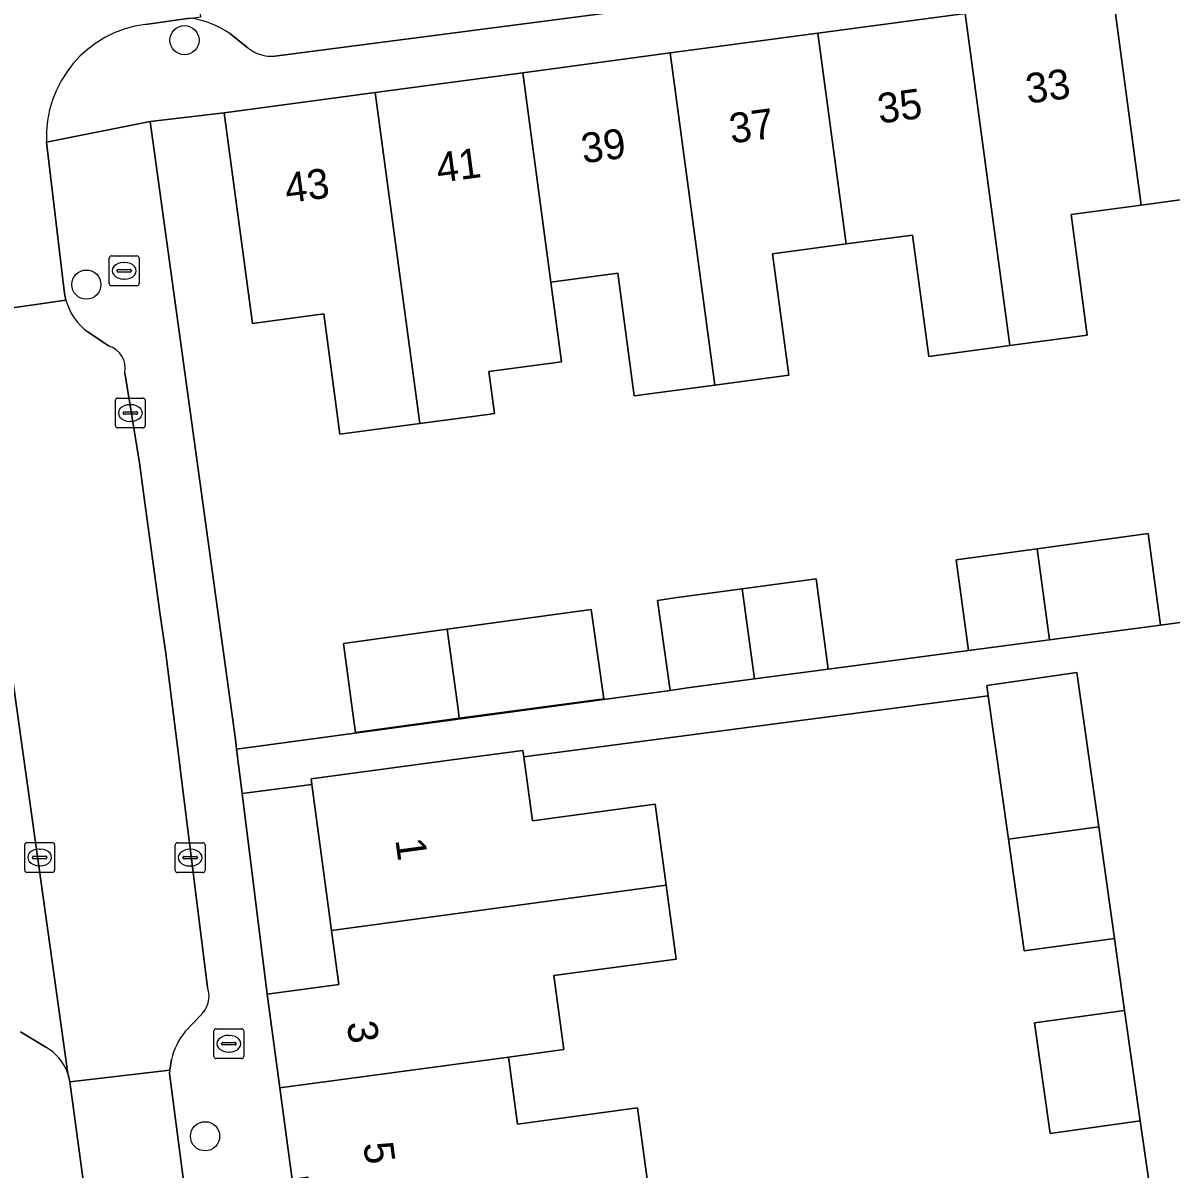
# Model space of a CAD drawing. Extents: x 163147 to 163550, y 380933 to 381639.
# Drawn here: x 163253.82 to 163292.27, y 381438.36 to 381476.76 of the extents above; entities that cross this region are included whole.
import ezdxf

# ---------------------------------------------------------------- set-up
doc = ezdxf.new("R2010")
doc.units = 0
for name, color, linetype in [('IMGEO_Boom', 7, 'Continuous'), ('IMGEO_Brandkraan', 7, 'Continuous'), ('IMGEO_Erf', 7, 'Continuous'), ('IMGEO_Kolk', 7, 'Continuous'), ('IMGEO_Muur', 7, 'Continuous'), ('IMGEO_Pand', 7, 'Continuous'), ('IMGEO_Pand_nummerreeks', 7, 'Continuous'), ('IMGEO_Parkeervlak_open', 7, 'Continuous'), ('IMGEO_Rijbaan_lokaal_open', 7, 'Continuous'), ('IMGEO_Voetpad_open', 7, 'Continuous')]:
    doc.layers.add(name, color=color, linetype=linetype)

msp = doc.modelspace()

# ---------------------------------------------------------------- linework, layer by layer
at = {"layer": 'IMGEO_Boom'}
for centre in [(163259.225, 381476.182), (163255.939, 381467.993), (163259.915, 381439.458)]:
    msp.add_circle(centre, 0.489, dxfattribs=at)
at = {"layer": 'IMGEO_Brandkraan'}
for p, q in [((163256.706, 381468.031), (163256.706, 381468.883)), ((163256.781, 381468.957), (163257.633, 381468.957)), ((163257.194, 381468.737), (163257.219, 381468.737)), ((163257.707, 381468.883), (163257.707, 381468.031)), ((163256.965, 381468.451), (163256.965, 381468.463)), ((163257.403, 381468.414), (163257.005, 381468.414)), ((163257.008, 381468.5), (163257.406, 381468.5)), ((163257.449, 381468.463), (163257.449, 381468.451)), ((163257.633, 381467.957), (163256.781, 381467.957)), ((163257.217, 381468.177), (163257.192, 381468.177)), ((163260.212, 381442.134), (163260.212, 381442.986)), ((163260.287, 381443.06), (163261.139, 381443.06)), ((163261.213, 381442.986), (163261.213, 381442.134)), ((163260.471, 381442.554), (163260.471, 381442.566)), ((163260.514, 381442.603), (163260.912, 381442.603)), ((163260.7, 381442.84), (163260.725, 381442.84)), ((163260.955, 381442.566), (163260.955, 381442.554)), ((163260.909, 381442.517), (163260.511, 381442.517)), ((163260.723, 381442.28), (163260.698, 381442.28)), ((163261.139, 381442.06), (163260.287, 381442.06))]:
    msp.add_line(p, q, dxfattribs=at)
for points in [[(163256.706, 381468.031), (163256.706, 381468.883)], [(163256.781, 381468.957), (163257.633, 381468.957)], [(163257.707, 381468.883), (163257.707, 381468.031)], [(163257.633, 381467.957), (163256.781, 381467.957)], [(163260.212, 381442.134), (163260.212, 381442.986)], [(163260.287, 381443.06), (163261.139, 381443.06)], [(163261.213, 381442.986), (163261.213, 381442.134)], [(163261.139, 381442.06), (163260.287, 381442.06)]]:
    msp.add_lwpolyline(points, dxfattribs=at)
for centre, radius, start, end in [((163256.783, 381468.881), 0.0765, 91.552, 178.448), ((163256.783, 381468.881), 0.0765, 91.552, 178.448), ((163257.631, 381468.881), 0.0765, 1.552, 88.448), ((163257.631, 381468.881), 0.0765, 1.552, 88.448), ((163257.005, 381468.46), 0.0403, 85.8775, 175.7526), ((163257.002, 381468.45), 0.0366, 178.938, 274.7102), ((163257.406, 381468.457), 0.043, 264.8664, 352.4533), ((163257.41, 381468.462), 0.0386, 1.7309, 96.639), ((163256.783, 381468.033), 0.0765, 181.552, 268.448), ((163256.783, 381468.033), 0.0765, 181.552, 268.448), ((163257.631, 381468.033), 0.0765, 271.552, 358.448), ((163257.631, 381468.033), 0.0765, 271.552, 358.448), ((163260.289, 381442.984), 0.0765, 91.552, 178.448), ((163260.289, 381442.984), 0.0765, 91.552, 178.448), ((163261.137, 381442.984), 0.0765, 1.552, 88.448), ((163261.137, 381442.984), 0.0765, 1.552, 88.448), ((163260.511, 381442.563), 0.0403, 85.8775, 175.7526), ((163260.508, 381442.553), 0.0366, 178.938, 274.7102), ((163260.912, 381442.56), 0.043, 264.8664, 352.4533), ((163260.916, 381442.565), 0.0386, 1.7309, 96.639), ((163260.289, 381442.136), 0.0765, 181.552, 268.448), ((163260.289, 381442.136), 0.0765, 181.552, 268.448), ((163261.137, 381442.136), 0.0765, 271.552, 358.448), ((163261.137, 381442.136), 0.0765, 271.552, 358.448)]:
    msp.add_arc(centre, radius, start, end, dxfattribs=at)
for centre, major_axis, ratio, start_param, end_param in [((163257.193, 381468.457), (-0.387, 0.002), 0.722429, 4.712389, 7.853982), ((163257.218, 381468.457), (-0.39, 0.002), 0.717154, 1.570796, 4.712389), ((163260.699, 381442.56), (-0.387, 0.002), 0.722429, 4.712389, 7.853982), ((163260.724, 381442.56), (-0.39, 0.002), 0.717154, 1.570796, 4.712389)]:
    msp.add_ellipse(centre, major_axis=major_axis, ratio=ratio, start_param=start_param, end_param=end_param, dxfattribs=at)
at = {"layer": 'IMGEO_Erf'}
for points in [[(163293.552, 381470.963), (163291.273, 381470.657), (163288.923, 381470.341), (163289.465, 381466.3), (163286.874, 381465.952), (163284.155, 381465.587), (163283.608, 381469.655), (163281.387, 381469.357), (163278.919, 381469.025), (163279.465, 381464.959), (163276.991, 381464.627), (163274.288, 381464.264), (163273.736, 381468.377), (163271.498, 381468.076), (163271.856, 381465.407), (163269.422, 381465.08), (163269.611, 381463.677), (163269.387, 381463.647), (163267.104, 381463.34), (163264.431, 381462.981), (163263.89, 381467.013), (163261.502, 381466.693), (163260.555, 381473.749), (163258.081, 381473.453), (163260.561, 381455.423), (163260.929, 381452.748), (163260.969, 381452.43), (163275.498, 381454.399), (163275.068, 381457.415), (163275.645, 381457.494), (163277.907, 381457.801), (163280.381, 381458.138), (163280.788, 381455.109), (163285.48, 381455.731), (163285.071, 381458.776), (163287.788, 381459.145), (163291.505, 381459.651), (163291.917, 381456.584), (163293.141, 381456.746)], [(163294.836, 381414.98), (163291.235, 381439.976), (163288.217, 381439.55), (163287.693, 381443.264), (163290.714, 381443.672), (163290.544, 381444.873), (163290.373, 381446.082), (163287.352, 381445.674), (163286.825, 381449.415), (163286.148, 381454.214), (163270.591, 381452.177), (163270.881, 381450.03), (163274.99, 381450.586), (163275.358, 381447.868), (163275.692, 381445.395), (163271.593, 381444.841), (163271.928, 381442.362), (163270.08, 381442.113), (163270.102, 381441.951), (163270.384, 381439.863), (163274.402, 381440.407), (163274.768, 381437.7)]]:
    msp.add_lwpolyline(points, dxfattribs=at)
for points in [[(163273.274, 381454.113), (163268.43, 381453.468), (163264.949, 381452.989), (163264.908, 381453.295), (163264.548, 381455.971), (163268.029, 381456.45), (163272.846, 381457.113)], [(163263.492, 381451.248), (163261.154, 381450.941), (163261.99, 381444.222), (163264.399, 381444.548), (163264.154, 381446.357)]]:
    msp.add_lwpolyline(points, close=True, dxfattribs=at)
at = {"layer": 'IMGEO_Kolk'}
for p, q in [((163256.912, 381463.265), (163256.912, 381464.117)), ((163256.987, 381464.191), (163257.839, 381464.191)), ((163257.913, 381464.117), (163257.913, 381463.265)), ((163257.171, 381463.685), (163257.171, 381463.697)), ((163257.214, 381463.734), (163257.612, 381463.734)), ((163257.4, 381463.971), (163257.425, 381463.971)), ((163257.655, 381463.697), (163257.655, 381463.685)), ((163257.609, 381463.648), (163257.211, 381463.648)), ((163257.423, 381463.411), (163257.398, 381463.411)), ((163257.839, 381463.191), (163256.987, 381463.191)), ((163253.875, 381448.375), (163253.875, 381449.227)), ((163253.95, 381449.301), (163254.802, 381449.301)), ((163254.363, 381449.081), (163254.388, 381449.081)), ((163254.876, 381449.227), (163254.876, 381448.375)), ((163258.916, 381448.368), (163258.916, 381449.22)), ((163258.991, 381449.294), (163259.843, 381449.294)), ((163259.404, 381449.074), (163259.429, 381449.074)), ((163259.917, 381449.22), (163259.917, 381448.368)), ((163254.134, 381448.795), (163254.134, 381448.807)), ((163254.572, 381448.758), (163254.174, 381448.758)), ((163254.177, 381448.844), (163254.575, 381448.844)), ((163254.618, 381448.807), (163254.618, 381448.795)), ((163259.175, 381448.788), (163259.175, 381448.8)), ((163259.613, 381448.751), (163259.215, 381448.751)), ((163259.218, 381448.837), (163259.616, 381448.837)), ((163259.659, 381448.8), (163259.659, 381448.788)), ((163254.802, 381448.301), (163253.95, 381448.301)), ((163254.386, 381448.521), (163254.361, 381448.521)), ((163259.843, 381448.294), (163258.991, 381448.294)), ((163259.427, 381448.514), (163259.402, 381448.514))]:
    msp.add_line(p, q, dxfattribs=at)
for points in [[(163256.912, 381463.265), (163256.912, 381464.117)], [(163256.987, 381464.191), (163257.839, 381464.191)], [(163257.913, 381464.117), (163257.913, 381463.265)], [(163257.839, 381463.191), (163256.987, 381463.191)], [(163253.875, 381448.375), (163253.875, 381449.227)], [(163253.95, 381449.301), (163254.802, 381449.301)], [(163254.876, 381449.227), (163254.876, 381448.375)], [(163258.916, 381448.368), (163258.916, 381449.22)], [(163258.991, 381449.294), (163259.843, 381449.294)], [(163259.917, 381449.22), (163259.917, 381448.368)], [(163254.802, 381448.301), (163253.95, 381448.301)], [(163259.843, 381448.294), (163258.991, 381448.294)]]:
    msp.add_lwpolyline(points, dxfattribs=at)
for centre, radius, start, end in [((163256.989, 381464.115), 0.0765, 91.552, 178.448), ((163256.989, 381464.115), 0.0765, 91.552, 178.448), ((163257.837, 381464.115), 0.0765, 1.552, 88.448), ((163257.837, 381464.115), 0.0765, 1.552, 88.448), ((163257.211, 381463.694), 0.0403, 85.8775, 175.7526), ((163257.208, 381463.684), 0.0366, 178.938, 274.7102), ((163257.612, 381463.691), 0.043, 264.8664, 352.4533), ((163257.616, 381463.696), 0.0386, 1.7309, 96.639), ((163256.989, 381463.267), 0.0765, 181.552, 268.448), ((163256.989, 381463.267), 0.0765, 181.552, 268.448), ((163257.837, 381463.267), 0.0765, 271.552, 358.448), ((163257.837, 381463.267), 0.0765, 271.552, 358.448), ((163253.952, 381449.225), 0.0765, 91.552, 178.448), ((163253.952, 381449.225), 0.0765, 91.552, 178.448), ((163254.8, 381449.225), 0.0765, 1.552, 88.448), ((163254.8, 381449.225), 0.0765, 1.552, 88.448), ((163258.993, 381449.218), 0.0765, 91.552, 178.448), ((163258.993, 381449.218), 0.0765, 91.552, 178.448), ((163259.841, 381449.218), 0.0765, 1.552, 88.448), ((163259.841, 381449.218), 0.0765, 1.552, 88.448), ((163254.174, 381448.804), 0.0403, 85.8775, 175.7526), ((163254.171, 381448.794), 0.0366, 178.938, 274.7102), ((163254.575, 381448.801), 0.043, 264.8664, 352.4533), ((163254.579, 381448.806), 0.0386, 1.7309, 96.639), ((163259.215, 381448.797), 0.0403, 85.8775, 175.7526), ((163259.212, 381448.787), 0.0366, 178.938, 274.7102), ((163259.616, 381448.794), 0.043, 264.8664, 352.4533), ((163259.62, 381448.799), 0.0386, 1.7309, 96.639), ((163253.952, 381448.377), 0.0765, 181.552, 268.448), ((163253.952, 381448.377), 0.0765, 181.552, 268.448), ((163254.8, 381448.377), 0.0765, 271.552, 358.448), ((163254.8, 381448.377), 0.0765, 271.552, 358.448), ((163258.993, 381448.37), 0.0765, 181.552, 268.448), ((163258.993, 381448.37), 0.0765, 181.552, 268.448), ((163259.841, 381448.37), 0.0765, 271.552, 358.448), ((163259.841, 381448.37), 0.0765, 271.552, 358.448)]:
    msp.add_arc(centre, radius, start, end, dxfattribs=at)
for centre, major_axis, ratio, start_param, end_param in [((163257.399, 381463.691), (-0.387, 0.002), 0.722429, 4.712389, 7.853982), ((163257.424, 381463.691), (-0.39, 0.002), 0.717154, 1.570796, 4.712389), ((163254.362, 381448.801), (-0.387, 0.002), 0.722429, 4.712389, 7.853982), ((163254.387, 381448.801), (-0.39, 0.002), 0.717154, 1.570796, 4.712389), ((163259.403, 381448.794), (-0.387, 0.002), 0.722429, 4.712389, 7.853982), ((163259.428, 381448.794), (-0.39, 0.002), 0.717154, 1.570796, 4.712389)]:
    msp.add_ellipse(centre, major_axis=major_axis, ratio=ratio, start_param=start_param, end_param=end_param, dxfattribs=at)
at = {"layer": 'IMGEO_Muur'}
msp.add_lwpolyline([(163260.561, 381455.423), (163258.081, 381473.453)], dxfattribs=at)
at = {"layer": 'IMGEO_Pand'}
for points in [[(163296.756, 381467.285), (163295.262, 381478.409), (163290.321, 381477.746), (163291.273, 381470.657), (163293.552, 381470.963), (163294.094, 381466.927)], [(163285.379, 381477.082), (163286.874, 381465.952), (163289.465, 381466.3), (163288.923, 381470.341), (163291.273, 381470.657), (163290.321, 381477.746)], [(163285.379, 381477.082), (163280.438, 381476.419), (163281.387, 381469.357), (163283.608, 381469.655), (163284.155, 381465.587), (163286.874, 381465.952)], [(163280.438, 381476.419), (163275.497, 381475.755), (163276.991, 381464.627), (163279.465, 381464.959), (163278.919, 381469.025), (163281.387, 381469.357)], [(163271.498, 381468.076), (163273.736, 381468.377), (163274.288, 381464.264), (163276.991, 381464.627), (163275.497, 381475.755), (163270.556, 381475.092)], [(163265.615, 381474.428), (163267.104, 381463.34), (163269.387, 381463.647), (163269.611, 381463.677), (163269.422, 381465.08), (163271.856, 381465.407), (163271.498, 381468.076), (163270.556, 381475.092)], [(163265.615, 381474.428), (163260.555, 381473.749), (163261.502, 381466.693), (163263.89, 381467.013), (163264.431, 381462.981), (163267.104, 381463.34)], [(163287.788, 381459.145), (163288.199, 381456.091), (163291.917, 381456.584), (163291.505, 381459.651)], [(163287.788, 381459.145), (163285.071, 381458.776), (163285.48, 381455.731), (163288.199, 381456.091)], [(163277.907, 381457.801), (163278.313, 381454.781), (163280.788, 381455.109), (163280.381, 381458.138)], [(163277.907, 381457.801), (163275.645, 381457.494), (163275.068, 381457.415), (163275.498, 381454.399), (163276.074, 381454.484), (163278.313, 381454.781)], [(163268.029, 381456.45), (163268.389, 381453.774), (163268.43, 381453.468), (163273.274, 381454.113), (163272.846, 381457.113)], [(163268.029, 381456.45), (163264.548, 381455.971), (163264.908, 381453.295), (163264.949, 381452.989), (163268.43, 381453.468), (163268.389, 381453.774)], [(163289.116, 381454.992), (163286.098, 381454.566), (163286.148, 381454.214), (163286.825, 381449.415), (163289.846, 381449.822)], [(163270.591, 381452.177), (163270.562, 381452.389), (163268.437, 381452.102), (163263.467, 381451.43), (163263.492, 381451.248), (163264.154, 381446.357), (163275.358, 381447.868), (163274.99, 381450.586), (163270.881, 381450.03)], [(163289.846, 381449.822), (163286.825, 381449.415), (163287.352, 381445.674), (163290.373, 381446.082)], [(163271.593, 381444.841), (163275.692, 381445.395), (163275.358, 381447.868), (163264.154, 381446.357), (163264.399, 381444.548), (163261.99, 381444.222), (163262.415, 381441.079), (163270.08, 381442.113), (163271.928, 381442.362)], [(163290.714, 381443.672), (163287.693, 381443.264), (163288.217, 381439.55), (163291.235, 381439.976)], [(163274.402, 381440.407), (163270.384, 381439.863), (163270.102, 381441.951), (163270.08, 381442.113), (163262.415, 381441.079), (163262.83, 381438.012), (163263.362, 381438.084), (163263.617, 381436.197), (163274.768, 381437.7)]]:
    msp.add_lwpolyline(points, close=True, dxfattribs=at)
at = {"layer": 'IMGEO_Parkeervlak_open'}
for points in [[(163262.25, 381475.647), (163279.275, 381477.871)], [(163260.742, 381476.403), (163261.35, 381475.931)], [(163255.318, 381441.565), (163251.818, 381466.551)], [(163253.738, 381442.963), (163254.58, 381442.446)]]:
    msp.add_lwpolyline(points, dxfattribs=at)
for centre, radius, start, end in [((163258.95, 381473.807), 3.154, 55.3844, 80.829), ((163262.136, 381476.855), 1.213, 229.602, 275.3712), ((163253.78, 381441.026), 1.63, 19.3054, 60.5993)]:
    msp.add_arc(centre, radius, start, end, dxfattribs=at)
at = {"layer": 'IMGEO_Rijbaan_lokaal_open'}
for points in [[(163257.917, 381476.713), (163259.249, 381476.896), (163259.453, 381476.921), (163259.772, 381476.964), (163259.34, 381480.286), (163259.216, 381480.261), (163257.16, 381480.189), (163255.891, 381480.145), (163252.977, 381480.049), (163249.798, 381480.397), (163248.73, 381480.753), (163248.478, 381480.841), (163246.169, 381474.213), (163246.738, 381474.018)], [(163251.475, 381468.994), (163251.759, 381466.968), (163255.257, 381467.47), (163255.209, 381467.701), (163254.604, 381472.77)], [(163255.257, 381467.47), (163251.759, 381466.968), (163251.818, 381466.551), (163255.318, 381441.565), (163255.377, 381441.352), (163255.386, 381441.283), (163258.739, 381441.673), (163258.787, 381442.035)], [(163256.68, 381465.942), (163255.99, 381466.411)], [(163258.597, 381455.641), (163258.412, 381456.927), (163257.898, 381460.677), (163257.717, 381462.026), (163257.23, 381465.042)], [(163260.001, 381444.445), (163258.597, 381455.641)], [(163259.252, 381442.964), (163259.752, 381443.494)]]:
    msp.add_lwpolyline(points, dxfattribs=at)
msp.add_lwpolyline([(163258.724, 381441.564), (163258.739, 381441.673), (163255.386, 381441.283), (163256.033, 381436.508), (163256.078, 381436.175), (163259.382, 381436.565), (163259.331, 381436.948)], close=True, dxfattribs=at)
for centre, radius, start, end in [((163258.401, 381472.943), 3.801, 97.3209, 182.6036), ((163257.108, 381467.968), 1.917, 195.0648, 234.3143), ((163256.46, 381465.189), 0.784, 349.1828, 73.6764), ((163259.155, 381444.158), 0.893, 311.9521, 18.7032), ((163261.013, 381441.501), 2.29, 140.297, 166.5236)]:
    msp.add_arc(centre, radius, start, end, dxfattribs=at)
at = {"layer": 'IMGEO_Voetpad_open'}
for points in [[(163254.604, 381472.77), (163258.081, 381473.453), (163260.555, 381473.749), (163265.615, 381474.428), (163270.556, 381475.092), (163275.497, 381475.755), (163280.438, 381476.419), (163285.379, 381477.082), (163290.321, 381477.746), (163295.262, 381478.409), (163300.203, 381479.073)], [(163279.275, 381477.871), (163262.25, 381475.647)], [(163259.453, 381476.921), (163259.249, 381476.896), (163257.917, 381476.713)], [(163261.35, 381475.931), (163260.742, 381476.403)], [(163266.729, 381409.746), (163266.721, 381409.809), (163266.516, 381411.222), (163265.512, 381418.124), (163265.087, 381421.261), (163264.673, 381424.321), (163265.214, 381424.394), (163264.958, 381426.288), (163264.288, 381431.242), (163263.617, 381436.197), (163263.362, 381438.084), (163262.83, 381438.012), (163262.415, 381441.079), (163261.99, 381444.222), (163261.154, 381450.941), (163260.969, 381452.43), (163260.929, 381452.748), (163260.561, 381455.423), (163258.081, 381473.453), (163254.604, 381472.77), (163255.209, 381467.701), (163255.257, 381467.47)], [(163255.99, 381466.411), (163256.68, 381465.942)], [(163257.23, 381465.042), (163257.717, 381462.026), (163257.898, 381460.677), (163258.412, 381456.927), (163258.597, 381455.641), (163260.001, 381444.445)], [(163293.141, 381456.746), (163291.917, 381456.584), (163288.199, 381456.091), (163285.48, 381455.731), (163280.788, 381455.109), (163278.313, 381454.781), (163276.074, 381454.484), (163275.498, 381454.399), (163260.969, 381452.43), (163261.154, 381450.941), (163263.492, 381451.248), (163263.467, 381451.43), (163268.437, 381452.102), (163270.562, 381452.389), (163270.591, 381452.177), (163286.148, 381454.214), (163286.098, 381454.566), (163289.116, 381454.992), (163289.846, 381449.822), (163290.373, 381446.082), (163290.544, 381444.873), (163290.714, 381443.672), (163291.235, 381439.976), (163294.836, 381414.98)], [(163259.752, 381443.494), (163259.252, 381442.964)], [(163254.58, 381442.446), (163253.738, 381442.963)], [(163258.787, 381442.035), (163258.739, 381441.673), (163258.724, 381441.564), (163259.331, 381436.948), (163259.382, 381436.565), (163259.399, 381436.434)], [(163256.078, 381436.175), (163256.033, 381436.508), (163255.386, 381441.283), (163255.377, 381441.352), (163255.318, 381441.565)]]:
    msp.add_lwpolyline(points, dxfattribs=at)
for centre, radius, start, end in [((163258.95, 381473.807), 3.154, 55.3844, 80.829), ((163258.401, 381472.943), 3.801, 97.3209, 182.6036), ((163262.136, 381476.855), 1.213, 229.602, 275.3712), ((163257.108, 381467.968), 1.917, 195.0648, 234.3143), ((163256.46, 381465.189), 0.784, 349.1828, 73.6764), ((163259.155, 381444.158), 0.893, 311.9521, 18.7032), ((163261.013, 381441.501), 2.29, 140.297, 166.5236), ((163253.78, 381441.026), 1.63, 19.3054, 60.5993)]:
    msp.add_arc(centre, radius, start, end, dxfattribs=at)

# ---------------------------------------------------------------- texts
at = {"layer": 'IMGEO_Pand_nummerreeks'}
for s, rotation, p in [('33', 7.6476, (163287.468, 381474.053)), ('35', 7.6476, (163282.505, 381473.386)), ('37', 7.6476, (163277.542, 381472.72)), ('39', 7.6476, (163272.58, 381472.054)), ('41', 7.6476, (163267.729, 381471.402)), ('43', 7.6476, (163262.654, 381470.721)), ('1', 277.7118, (163266.286, 381449.392)), ('3', 277.7061, (163264.663, 381443.261)), ('5', 277.6774, (163265.21, 381439.212))]:
    msp.add_text(s, height=1, rotation=rotation, dxfattribs=at).set_placement(p)

doc.saveas('drawing.dxf')
